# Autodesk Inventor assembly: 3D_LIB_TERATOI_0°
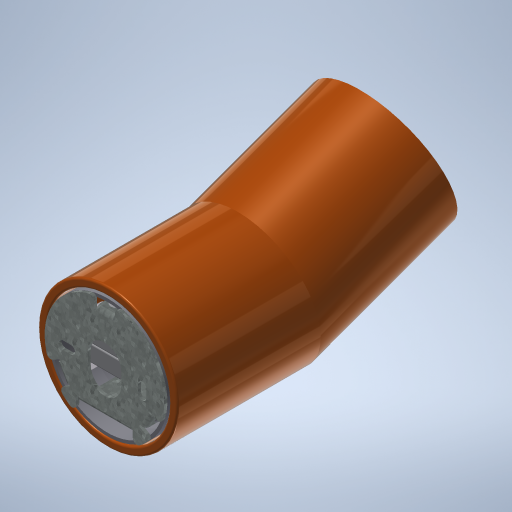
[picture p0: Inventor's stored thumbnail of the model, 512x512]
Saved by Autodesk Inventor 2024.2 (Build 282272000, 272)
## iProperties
Manager: DarkStudio
Company: DARK
Created: 2022-11
Part Number: 3D_LIB_TERATOI_0°
Document SubType Name: Assembly
Designer: DarkStudio
Engineer: DarkStudio
Project: 444 - TERATOI
Description: TERATOI - 20°
Author: DarkStudio
Revision Number: V2
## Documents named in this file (19)
- C:\Users\Stage\Desktop\Stage Karsten\armatures\444 - TERATOI\V4\444_KARSTEN\3D_LIB_TERATOI_0°.iam
- C:\Users\Stage\Desktop\Stage Karsten\armatures\444 - TERATOI\V4\444-002.ipt
- C:\Users\Stage\Desktop\Stage Karsten\armatures\444 - TERATOI\V4\Veerring DIN 6798 M4.ipt
- C:\Users\Stage\Desktop\Stage Karsten\armatures\444 - TERATOI\V4\GU10 - SPOT.ipt
- C:\Users\Stage\Desktop\Stage Karsten\armatures\444 - TERATOI\V4\GU10 BJB 25.819.ipt
- C:\Users\Stage\Desktop\Stage Karsten\armatures\444 - TERATOI\V4\444-004.ipt
- C:\Users\Stage\Desktop\Stage Karsten\armatures\444 - TERATOI\V4\444-006.ipt
- C:\Users\Stage\Desktop\Stage Karsten\armatures\444 - TERATOI\V4\Trompetnippel platte kanten M10 x 1 x 10.ipt
- C:\Users\Stage\Desktop\Stage Karsten\armatures\444 - TERATOI\V4\fiberring 14x10x1mm.ipt
- C:\Users\Stage\Desktop\Stage Karsten\armatures\444 - TERATOI\V4\82297000 -0-000 = 092-018.ipt
- C:\Users\Stage\Desktop\Stage Karsten\armatures\444 - TERATOI\V4\444-009.ipt
- C:\Users\Stage\Desktop\Stage Karsten\armatures\444 - TERATOI\V4\poprivet 2.9 x 5.ipt
- C:\Users\Stage\Desktop\Stage Karsten\armatures\444 - TERATOI\V4\DIN 7985 M4  x 6.ipt
- C:\Users\Stage\Desktop\Stage Karsten\armatures\444 - TERATOI\V4\444-010.ipt
- C:\Users\Stage\Desktop\Stage Karsten\armatures\444 - TERATOI\V4\DIN 7985 M3 x 4.ipt
- C:\Users\Stage\Desktop\Stage Karsten\armatures\444 - TERATOI\V4\Bendler_Platte_Din6879a.ipt
- C:\Users\Stage\Desktop\TUUR\2D en 3D\TERATOI\444 - TERATOI\V4\DIN 7985 M3 x 8.ipt
- C:\Users\Stage\Desktop\Stage Karsten\armatures\444 - TERATOI\V4\444-011.ipt
- C:\Users\Stage\Desktop\Stage Karsten\armatures\444 - TERATOI\V4\WAGO 221-413_2_14 splicing connector 3P.ipt
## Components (24 placed, 18 different names)
1. 444-002:1 — Mate:53, Flush:4, Mate:64, Mate:65, Flush:77, Mate:76
2. 444-006:1 — Mate:49, Mate:50, Mate:74, Flush:77, Mate:76
3. 444-004:1
4. GU10 BJB 25.819:1 — Mate:84
5. GU10 - SPOT:1 — Mate:74
6. DIN 7985 M3 x 12:2
7. DIN 7985 M3 x 12:1
8. Trompetnippel platte kanten M10 x 1 x 10:1 — Mate:45, Mate:47, Mate:66, Mate:69, Angle:2, Mate:80
9. 444-011:1 — Mate:84
10. fiberring 14x10x1mm:1 — Mate:45, Mate:46
11. 82297000 -0-000 = 092-018:1 — Mate:46, Mate:47, Mate:71
12. DIN 7985 M4  x 6:1 — Mate:59, Mate:60
13. Veerring DIN 6798 M4:2 — Mate:60, Mate:61
14. 444-010:1
15. DIN 7985 M3 x 4:1 — Mate:65, Flush:5
16. Bendler_Platte_Din6879a:1 — Mate:69, Mate:71
17. WAGO 221-413_2_14 splicing connector 3P:1 — Mate:86, Mate:87
18. WAGO 221-413_2_14 splicing connector 3P:2
19. 444-009:1 — Mate:55, Mate:56, Angle:1
20. poprivet 2.9 x 5:1 — Mate:54, Mate:56, Mate:57
21. 444-009:2
22. poprivet 2.9 x 5:2
23. 444-009:3
24. poprivet 2.9 x 5:3
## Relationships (29: Mate 24, Flush 3, Angle 2)
- Mate:45: Trompetnippel platte kanten M10 x 1 x 10:1 ↔ fiberring 14x10x1mm:1
- Mate:46: fiberring 14x10x1mm:1 ↔ 82297000 -0-000 = 092-018:1
- Mate:47: Trompetnippel platte kanten M10 x 1 x 10:1 ↔ 82297000 -0-000 = 092-018:1
- Mate:49: 444-006:1
- Mate:50: 444-006:1
- Mate:53: 444-002:1
- Mate:54: poprivet 2.9 x 5:1
- Mate:55: 444-009:1
- Mate:56: 444-009:1 ↔ poprivet 2.9 x 5:1
- Angle:1: 444-009:1
- Mate:57: poprivet 2.9 x 5:1
- Mate:59: DIN 7985 M4  x 6:1
- Mate:60: DIN 7985 M4  x 6:1 ↔ Veerring DIN 6798 M4:2
- Mate:61: Veerring DIN 6798 M4:2
- Flush:4: 444-002:1
- Mate:64: 444-002:1
- Mate:65: 444-002:1 ↔ DIN 7985 M3 x 4:1
- Flush:5: DIN 7985 M3 x 4:1
- Mate:66: Trompetnippel platte kanten M10 x 1 x 10:1
- Mate:69: Trompetnippel platte kanten M10 x 1 x 10:1 ↔ Bendler_Platte_Din6879a:1
- Mate:71: 82297000 -0-000 = 092-018:1 ↔ Bendler_Platte_Din6879a:1
- Mate:74: 444-006:1 ↔ GU10 - SPOT:1
- Flush:77: 444-002:1 ↔ 444-006:1
- Mate:76: 444-002:1 ↔ 444-006:1
- Angle:2: Trompetnippel platte kanten M10 x 1 x 10:1
- Mate:80: Trompetnippel platte kanten M10 x 1 x 10:1
- Mate:84: GU10 BJB 25.819:1 ↔ 444-011:1
- Mate:86: WAGO 221-413_2_14 splicing connector 3P:1
- Mate:87: WAGO 221-413_2_14 splicing connector 3P:1
## Named parameters: d81_d54 = 0, d85_d65 = 0, d86_d63 = 0, d121_d68 = 0, d122_d69 = 0, d123_d70 = 0
